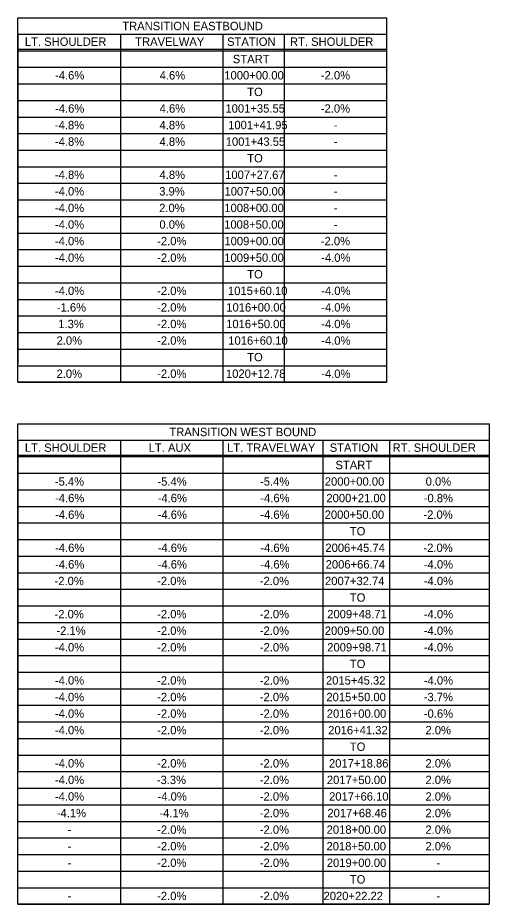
# Model space of a CAD drawing. Extents: x -15318841 to 1762012, y 465773 to 3693661.
# Drawn here: x -15310976.2 to -15310807.3, y 3691124.6 to 3691442.4 of the extents above; entities that cross this region are included whole.
import ezdxf

# ---------------------------------------------------------------- set-up
doc = ezdxf.new("R2010")
doc.units = 0
doc.layers.add('BORDER', color=7, linetype='Continuous')
doc.layers.add('DIMENSIONS', color=7, linetype='Continuous')

msp = doc.modelspace()

# ---------------------------------------------------------------- linework, layer by layer
at = {"layer": 'BORDER'}
for p, q in [((-15310976.23, 3691436.42), (-15310976.23, 3691318.22)), ((-15310939.46, 3691436.42), (-15310939.46, 3691311.69)), ((-15310902.69, 3691436.42), (-15310902.69, 3691311.69)), ((-15310880.82, 3691436.42), (-15310880.82, 3691311.69)), ((-15310976.23, 3691431.14), (-15310844.05, 3691431.14)), ((-15310976.23, 3691430.54), (-15310844.05, 3691430.54)), ((-15310976.23, 3691424.6), (-15310844.05, 3691424.6)), ((-15310976.23, 3691424.6), (-15310844.05, 3691424.6)), ((-15310976.23, 3691424.6), (-15310844.05, 3691424.6)), ((-15310976.23, 3691418.66), (-15310844.05, 3691418.66)), ((-15310976.23, 3691412.71), (-15310844.05, 3691412.71)), ((-15310976.23, 3691406.77), (-15310844.05, 3691406.77)), ((-15310976.23, 3691400.83), (-15310844.05, 3691400.83)), ((-15310976.23, 3691394.88), (-15310844.05, 3691394.88)), ((-15310976.23, 3691388.94), (-15310844.05, 3691388.94)), ((-15310976.23, 3691383), (-15310844.05, 3691383)), ((-15310976.23, 3691377.06), (-15310844.05, 3691377.06)), ((-15310976.23, 3691371.11), (-15310844.05, 3691371.11)), ((-15310976.23, 3691365.17), (-15310844.05, 3691365.17)), ((-15310976.23, 3691359.23), (-15310844.05, 3691359.23)), ((-15310976.23, 3691353.29), (-15310844.05, 3691353.29)), ((-15310976.23, 3691347.34), (-15310844.05, 3691347.34)), ((-15310976.23, 3691341.4), (-15310844.05, 3691341.4)), ((-15310976.23, 3691335.46), (-15310844.05, 3691335.46)), ((-15310976.23, 3691329.51), (-15310844.05, 3691329.51)), ((-15310976.23, 3691323.57), (-15310844.05, 3691323.57)), ((-15310976.23, 3691317.63), (-15310844.05, 3691317.63)), ((-15310976.23, 3691311.69), (-15310844.05, 3691311.69)), ((-15310976.23, 3691290.9), (-15310976.23, 3691172.7)), ((-15310939.46, 3691290.9), (-15310939.46, 3691124.56)), ((-15310902.69, 3691290.9), (-15310902.69, 3691124.56)), ((-15310866.92, 3691290.9), (-15310866.92, 3691124.56)), ((-15310843.05, 3691290.9), (-15310843.05, 3691124.56)), ((-15310976.23, 3691285.61), (-15310807.28, 3691285.61)), ((-15310976.23, 3691285.02), (-15310807.28, 3691285.02)), ((-15310976.23, 3691279.08), (-15310807.28, 3691279.08)), ((-15310976.23, 3691279.08), (-15310807.28, 3691279.08)), ((-15310976.23, 3691279.08), (-15310807.28, 3691279.08)), ((-15310976.23, 3691273.13), (-15310807.28, 3691273.13)), ((-15310976.23, 3691267.19), (-15310807.28, 3691267.19)), ((-15310976.23, 3691261.25), (-15310807.28, 3691261.25)), ((-15310976.23, 3691255.3), (-15310807.28, 3691255.3)), ((-15310976.23, 3691249.36), (-15310807.28, 3691249.36)), ((-15310976.23, 3691243.42), (-15310807.28, 3691243.42)), ((-15310976.23, 3691237.48), (-15310807.28, 3691237.48)), ((-15310976.23, 3691231.53), (-15310807.28, 3691231.53)), ((-15310976.23, 3691225.59), (-15310807.28, 3691225.59)), ((-15310976.23, 3691219.65), (-15310807.28, 3691219.65)), ((-15310976.23, 3691213.71), (-15310807.28, 3691213.71)), ((-15310976.23, 3691207.76), (-15310807.28, 3691207.76)), ((-15310976.23, 3691201.82), (-15310807.28, 3691201.82)), ((-15310976.23, 3691195.88), (-15310807.28, 3691195.88)), ((-15310976.23, 3691189.93), (-15310807.28, 3691189.93)), ((-15310976.23, 3691183.99), (-15310807.28, 3691183.99)), ((-15310976.23, 3691178.05), (-15310807.28, 3691178.05)), ((-15310976.23, 3691172.11), (-15310807.28, 3691172.11)), ((-15310976.23, 3691166.16), (-15310807.28, 3691166.16)), ((-15310976.23, 3691160.22), (-15310807.28, 3691160.22)), ((-15310976.23, 3691154.28), (-15310807.28, 3691154.28)), ((-15310976.23, 3691148.34), (-15310807.28, 3691148.34)), ((-15310976.23, 3691142.39), (-15310807.28, 3691142.39)), ((-15310976.23, 3691136.45), (-15310807.28, 3691136.45)), ((-15310976.23, 3691130.51), (-15310807.28, 3691130.51)), ((-15310976.23, 3691124.56), (-15310807.28, 3691124.56))]:
    msp.add_line(p, q, dxfattribs=at)
for points in [[(-15310976.23, 3691436.42), (-15310976.23, 3691442.36), (-15310844.05, 3691442.36), (-15310844.05, 3691436.42)], [(-15310976.23, 3691290.9), (-15310976.23, 3691296.84), (-15310807.28, 3691296.84), (-15310807.28, 3691290.9)]]:
    msp.add_lwpolyline(points, dxfattribs=at)
for points in [[(-15310976.23, 3691436.42), (-15310844.05, 3691436.42), (-15310844.05, 3691311.69), (-15310976.23, 3691311.69)], [(-15310976.23, 3691290.9), (-15310807.28, 3691290.9), (-15310807.28, 3691124.56), (-15310976.23, 3691124.56)]]:
    msp.add_lwpolyline(points, close=True, dxfattribs=at)

# ---------------------------------------------------------------- texts
at = {"layer": 'DIMENSIONS'}
for s, p in [('TRANSITION EASTBOUND', (-15310938.78, 3691437.89)), ('LT. SHOULDER', (-15310973.67, 3691432.28)), ('TRAVELWAY', (-15310934.14, 3691432.28)), ('STATION', (-15310901.23, 3691432.28)), ('RT. SHOULDER', (-15310878.69, 3691432.28)), ('START', (-15310899.15, 3691426.05)), ('-4.6%', (-15310962.85, 3691420.22)), ('4.6%', (-15310925.37, 3691420.22)), ('1000+00.00', (-15310902.21, 3691420.22)), ('-2.0%', (-15310867.63, 3691420.22)), ('TO', (-15310894, 3691414.28)), ('-4.6%', (-15310962.85, 3691408.34)), ('4.6%', (-15310925.37, 3691408.34)), ('1001+35.55', (-15310901.8, 3691408.34)), ('-2.0%', (-15310867.63, 3691408.34)), ('-4.8%', (-15310962.9, 3691402.4)), ('4.8%', (-15310925.42, 3691402.4)), ('1001+41.95', (-15310900.83, 3691402.4)), ('-', (-15310862.94, 3691402.4)), ('-4.8%', (-15310962.9, 3691396.45)), ('4.8%', (-15310925.42, 3691396.45)), ('1001+43.55', (-15310901.71, 3691396.45)), ('-', (-15310862.94, 3691396.45)), ('TO', (-15310894, 3691390.51)), ('-4.8%', (-15310962.9, 3691384.57)), ('4.8%', (-15310925.42, 3691384.57)), ('1007+27.67', (-15310901.91, 3691384.57)), ('-', (-15310862.94, 3691384.57)), ('-4.0%', (-15310962.9, 3691378.63)), ('3.9%', (-15310925.54, 3691378.63)), ('1007+50.00', (-15310902.14, 3691378.63)), ('-', (-15310862.94, 3691378.63)), ('-4.0%', (-15310962.9, 3691372.68)), ('2.0%', (-15310925.56, 3691372.68)), ('1008+00.00', (-15310902.21, 3691372.68)), ('-', (-15310862.94, 3691372.68)), ('-4.0%', (-15310962.9, 3691366.74)), ('0.0%', (-15310925.47, 3691366.74)), ('1008+50.00', (-15310902.26, 3691366.74)), ('-', (-15310862.94, 3691366.74)), ('-4.0%', (-15310962.9, 3691360.8)), ('-2.0%', (-15310926.27, 3691360.8)), ('1009+00.00', (-15310902.17, 3691360.8)), ('-2.0%', (-15310867.63, 3691360.8)), ('-4.0%', (-15310962.9, 3691354.85)), ('-2.0%', (-15310926.27, 3691354.85)), ('1009+50.00', (-15310902.21, 3691354.85)), ('-4.0%', (-15310867.49, 3691354.85)), ('TO', (-15310894, 3691348.91)), ('-4.0%', (-15310962.9, 3691342.97)), ('-2.0%', (-15310926.27, 3691342.97)), ('1015+60.10', (-15310900.89, 3691342.97)), ('-4.0%', (-15310867.49, 3691342.97)), ('-1.6%', (-15310962.23, 3691337.03)), ('-2.0%', (-15310926.27, 3691337.03)), ('1016+00.00', (-15310901.51, 3691337.03)), ('-4.0%', (-15310867.49, 3691337.03)), ('1.3%', (-15310961.69, 3691331.08)), ('-2.0%', (-15310926.27, 3691331.08)), ('1016+50.00', (-15310901.55, 3691331.08)), ('-4.0%', (-15310867.49, 3691331.08)), ('2.0%', (-15310962.33, 3691325.14)), ('-2.0%', (-15310926.27, 3691325.14)), ('1016+60.10', (-15310900.8, 3691325.14)), ('-4.0%', (-15310867.49, 3691325.14)), ('TO', (-15310894, 3691319.2)), ('2.0%', (-15310962.33, 3691313.26)), ('-2.0%', (-15310926.27, 3691313.26)), ('1020+12.78', (-15310901.61, 3691313.26)), ('-4.0%', (-15310867.49, 3691313.26)), ('TRANSITION WEST BOUND', (-15310921.88, 3691292.37)), ('LT. SHOULDER', (-15310973.67, 3691286.75)), ('LT. AUX', (-15310929.31, 3691286.75)), ('LT. TRAVELWAY', (-15310901.24, 3691286.75)), ('STATION', (-15310864.46, 3691286.75)), ('RT. SHOULDER', (-15310841.92, 3691286.75)), ('START', (-15310862.39, 3691280.53)), ('-5.4%', (-15310962.94, 3691274.62)), ('-5.4%', (-15310926.18, 3691274.62)), ('-5.4%', (-15310889.41, 3691274.62)), ('2000+00.00', (-15310866.2, 3691274.62)), ('0.0%', (-15310830.06, 3691274.62)), ('-4.6%', (-15310962.85, 3691268.68)), ('-4.6%', (-15310926.08, 3691268.68)), ('-4.6%', (-15310889.31, 3691268.68)), ('2000+21.00', (-15310865.64, 3691268.68)), ('-0.8%', (-15310830.76, 3691268.68)), ('-4.6%', (-15310962.85, 3691262.73)), ('-4.6%', (-15310926.08, 3691262.73)), ('-4.6%', (-15310889.31, 3691262.73)), ('2000+50.00', (-15310866.25, 3691262.73)), ('-2.0%', (-15310830.86, 3691262.73)), ('TO', (-15310857.23, 3691256.79)), ('-4.6%', (-15310962.85, 3691250.85)), ('-4.6%', (-15310926.08, 3691250.85)), ('-4.6%', (-15310889.31, 3691250.85)), ('2006+45.74', (-15310865.99, 3691250.85)), ('-2.0%', (-15310830.86, 3691250.85)), ('-4.6%', (-15310962.85, 3691244.91)), ('-4.6%', (-15310926.08, 3691244.91)), ('-4.6%', (-15310889.31, 3691244.91)), ('2006+66.74', (-15310865.9, 3691244.91)), ('-4.0%', (-15310830.72, 3691244.91)), ('-2.0%', (-15310963.04, 3691238.96)), ('-2.0%', (-15310926.27, 3691238.96)), ('-2.0%', (-15310889.5, 3691238.96)), ('2007+32.74', (-15310866.13, 3691238.96)), ('-4.0%', (-15310830.72, 3691238.96)), ('TO', (-15310857.23, 3691233.02)), ('-2.0%', (-15310963.04, 3691227.08)), ('-2.0%', (-15310926.27, 3691227.08)), ('-2.0%', (-15310889.5, 3691227.08)), ('2009+48.71', (-15310865.33, 3691227.08)), ('-4.0%', (-15310830.72, 3691227.08)), ('-2.1%', (-15310962.38, 3691221.14)), ('-2.0%', (-15310926.27, 3691221.14)), ('-2.0%', (-15310889.5, 3691221.14)), ('2009+50.00', (-15310866.2, 3691221.14)), ('-4.0%', (-15310830.72, 3691221.14)), ('-4.0%', (-15310962.9, 3691215.19)), ('-2.0%', (-15310926.27, 3691215.19)), ('-2.0%', (-15310889.5, 3691215.19)), ('2009+98.71', (-15310865.33, 3691215.19)), ('-4.0%', (-15310830.72, 3691215.19)), ('TO', (-15310857.23, 3691209.25)), ('-4.0%', (-15310962.9, 3691203.31)), ('-2.0%', (-15310926.27, 3691203.31)), ('-2.0%', (-15310889.5, 3691203.31)), ('2015+45.32', (-15310865.79, 3691203.31)), ('-4.0%', (-15310830.72, 3691203.31)), ('-4.0%', (-15310962.9, 3691197.36)), ('-2.0%', (-15310926.27, 3691197.36)), ('-2.0%', (-15310889.5, 3691197.36)), ('2015+50.00', (-15310865.64, 3691197.36)), ('-3.7%', (-15310830.77, 3691197.36)), ('-4.0%', (-15310962.9, 3691191.42)), ('-2.0%', (-15310926.27, 3691191.42)), ('-2.0%', (-15310889.5, 3691191.42)), ('2016+00.00', (-15310865.49, 3691191.42)), ('-0.6%', (-15310830.72, 3691191.42)), ('-4.0%', (-15310962.9, 3691185.48)), ('-2.0%', (-15310926.27, 3691185.48)), ('-2.0%', (-15310889.5, 3691185.48)), ('2016+41.32', (-15310864.99, 3691185.48)), ('2.0%', (-15310830.15, 3691185.48)), ('TO', (-15310857.23, 3691179.54)), ('-4.0%', (-15310962.9, 3691173.59)), ('-2.0%', (-15310926.27, 3691173.59)), ('-2.0%', (-15310889.5, 3691173.59)), ('2017+18.86', (-15310864.71, 3691173.59)), ('2.0%', (-15310830.15, 3691173.59)), ('-4.0%', (-15310962.9, 3691167.65)), ('-3.3%', (-15310926.41, 3691167.65)), ('-2.0%', (-15310889.5, 3691167.65)), ('2017+50.00', (-15310865.47, 3691167.65)), ('2.0%', (-15310830.15, 3691167.65)), ('-4.0%', (-15310962.9, 3691161.71)), ('-4.0%', (-15310926.13, 3691161.71)), ('-2.0%', (-15310889.5, 3691161.71)), ('2017+66.10', (-15310864.67, 3691161.71)), ('2.0%', (-15310830.15, 3691161.71)), ('-4.1%', (-15310962.23, 3691155.77)), ('-4.1%', (-15310925.47, 3691155.77)), ('-2.0%', (-15310889.5, 3691155.77)), ('2017+68.46', (-15310865.28, 3691155.77)), ('2.0%', (-15310830.15, 3691155.77)), ('-', (-15310958.35, 3691149.82)), ('-2.0%', (-15310926.27, 3691149.82)), ('-2.0%', (-15310889.5, 3691149.82)), ('2018+00.00', (-15310865.54, 3691149.82)), ('2.0%', (-15310830.15, 3691149.82)), ('-', (-15310958.35, 3691143.88)), ('-2.0%', (-15310926.27, 3691143.88)), ('-2.0%', (-15310889.5, 3691143.88)), ('2018+50.00', (-15310865.59, 3691143.88)), ('2.0%', (-15310830.15, 3691143.88)), ('-', (-15310958.35, 3691137.94)), ('-2.0%', (-15310926.27, 3691137.94)), ('-2.0%', (-15310889.5, 3691137.94)), ('2019+00.00', (-15310865.49, 3691137.94)), ('-', (-15310826.17, 3691137.94)), ('TO', (-15310857.23, 3691132)), ('-2.0%', (-15310926.27, 3691126.05)), ('-2.0%', (-15310889.5, 3691126.05)), ('2020+22.22', (-15310866.66, 3691126.05)), ('-', (-15310958.35, 3691126.05)), ('-', (-15310826.17, 3691126.05))]:
    msp.add_text(s, height=3, dxfattribs=at).set_placement(p)

doc.saveas('drawing.dxf')
